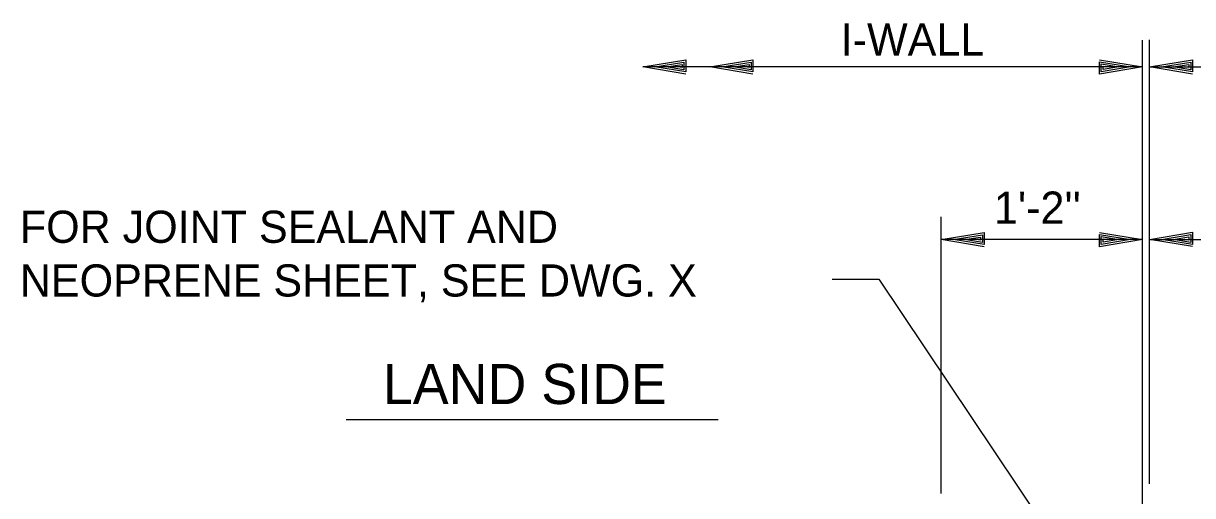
# Model space of a CAD drawing. Extents: x 22369.6 to 22428.3, y 22369.6 to 22415.
# Drawn here: x 22411.11 to 22417.89, y 22402.5 to 22405.24 of the extents above; entities that cross this region are included whole.
import ezdxf

# ---------------------------------------------------------------- set-up
doc = ezdxf.new("R2010")
doc.units = 0
for name, color, linetype in [('Level 1', 7, 'Continuous'), ('Level 10', 7, 'Continuous'), ('Level 2', 7, 'Continuous'), ('Level 4', 7, 'Continuous')]:
    doc.layers.add(name, color=color, linetype=linetype)

msp = doc.modelspace()

# ---------------------------------------------------------------- linework, layer by layer
at = {"layer": 'Level 1'}
for p, q in [((22417.5984, 22402.0943), (22417.5984, 22405.1431)), ((22417.6401, 22402.5671), (22417.6401, 22405.1464)), ((22417.5984, 22404.9883), (22414.7016, 22404.9883)), ((22417.6401, 22404.9883), (22420.9464, 22404.9883)), ((22416.4319, 22402.5107), (22416.4319, 22404.1174)), ((22417.5984, 22403.9859), (22416.4319, 22403.9859)), ((22417.6401, 22403.9871), (22419.6594, 22403.9871))]:
    msp.add_line(p, q, dxfattribs=at)
msp.add_lwpolyline([(22415.8004, 22403.7562), (22416.0693, 22403.7562), (22417.548, 22401.5457)], dxfattribs=at)
at = {"layer": 'Level 10'}
msp.add_line((22412.9817, 22402.941), (22415.1395, 22402.941), dxfattribs=at)
at = {"layer": 'Level 2'}
for p, q in [((22414.7016, 22404.9883), (22414.7016, 22404.9883)), ((22414.771, 22404.9883), (22414.771, 22404.9883)), ((22415.2963, 22404.9883), (22415.2963, 22404.9883)), ((22415.319, 22405.003), (22415.319, 22405.003)), ((22415.319, 22404.9843), (22415.319, 22404.9843)), ((22415.3296, 22405.0163), (22415.3296, 22405.0163)), ((22415.3403, 22405.0296), (22415.3403, 22405.0296)), ((22417.5291, 22404.9883), (22417.5291, 22404.9883)), ((22417.5984, 22404.9883), (22417.5984, 22404.9883)), ((22417.6401, 22404.9883), (22417.6401, 22404.9883)), ((22417.7094, 22404.9883), (22417.7094, 22404.9883)), ((22415.3296, 22404.971), (22415.3296, 22404.971)), ((22415.3403, 22404.959), (22415.3403, 22404.959)), ((22415.3403, 22404.947), (22415.3403, 22404.947)), ((22416.4319, 22403.9859), (22416.4319, 22403.9859)), ((22416.5012, 22403.9859), (22416.5012, 22403.9859)), ((22417.5291, 22403.9859), (22417.5291, 22403.9859)), ((22417.5984, 22403.9859), (22417.5984, 22403.9859)), ((22417.6401, 22403.9871), (22417.6401, 22403.9871)), ((22417.7094, 22403.9871), (22417.7094, 22403.9871))]:
    msp.add_line(p, q, dxfattribs=at)
for points in [[(22414.951, 22404.947), (22414.7016, 22404.9883), (22414.951, 22405.0296), (22414.951, 22404.959), (22414.771, 22404.9883), (22414.9403, 22405.0163), (22414.9403, 22404.971), (22414.8376, 22404.9883), (22414.9296, 22405.003), (22414.9296, 22404.9843), (22414.907, 22404.9883)], [(22415.3403, 22404.947), (22415.091, 22404.9883), (22415.3403, 22405.0296), (22415.3403, 22404.959), (22415.1603, 22404.9883), (22415.3296, 22405.0163), (22415.3296, 22404.971), (22415.227, 22404.9883), (22415.319, 22405.003), (22415.319, 22404.9843), (22415.2963, 22404.9883)], [(22417.3491, 22405.0296), (22417.5984, 22404.9883), (22417.3491, 22404.947), (22417.3491, 22405.0176), (22417.5291, 22404.9883), (22417.3598, 22404.9603), (22417.3598, 22405.0056), (22417.4624, 22404.9883), (22417.3704, 22404.9736), (22417.3704, 22404.9923), (22417.3931, 22404.9883)], [(22417.8894, 22404.947), (22417.6401, 22404.9883), (22417.8894, 22405.0296), (22417.8894, 22404.959), (22417.7094, 22404.9883), (22417.8788, 22405.0163), (22417.8788, 22404.971), (22417.7761, 22404.9883), (22417.8681, 22405.003), (22417.8681, 22404.9843), (22417.8454, 22404.9883)], [(22416.6812, 22403.9446), (22416.4319, 22403.9859), (22416.6812, 22404.0272), (22416.6812, 22403.9566), (22416.5012, 22403.9859), (22416.6705, 22404.0139), (22416.6705, 22403.9686), (22416.5679, 22403.9859), (22416.6599, 22404.0006), (22416.6599, 22403.9819), (22416.6372, 22403.9859)], [(22417.3491, 22404.0272), (22417.5984, 22403.9859), (22417.3491, 22403.9446), (22417.3491, 22404.0152), (22417.5291, 22403.9859), (22417.3598, 22403.9579), (22417.3598, 22404.0032), (22417.4624, 22403.9859), (22417.3704, 22403.9712), (22417.3704, 22403.9899), (22417.3931, 22403.9859)], [(22417.8894, 22403.9458), (22417.6401, 22403.9871), (22417.8894, 22404.0285), (22417.8894, 22403.9578), (22417.7094, 22403.9871), (22417.8788, 22404.0151), (22417.8788, 22403.9698), (22417.7761, 22403.9871), (22417.8681, 22404.0018), (22417.8681, 22403.9831), (22417.8454, 22403.9871)]]:
    msp.add_lwpolyline(points, dxfattribs=at)

# ---------------------------------------------------------------- texts
at = {"layer": 'Level 10'}
msp.add_text('LAND SIDE', height=0.23321, rotation=359.99999, dxfattribs=at).set_placement((22413.1943, 22403.0309))
at = {"layer": 'Level 4'}
for s, height, p in [('I-WALL', 0.18667, (22415.8493, 22405.0547)), ("1'-2''", 0.18667, (22416.738, 22404.0781)), ('FOR JOINT SEALANT AND', 0.186667, (22411.0892, 22403.967)), ('NEOPRENE SHEET, SEE DWG. X', 0.186667, (22411.0892, 22403.6553))]:
    msp.add_text(s, height=height, dxfattribs=at).set_placement(p)

doc.saveas('drawing.dxf')
